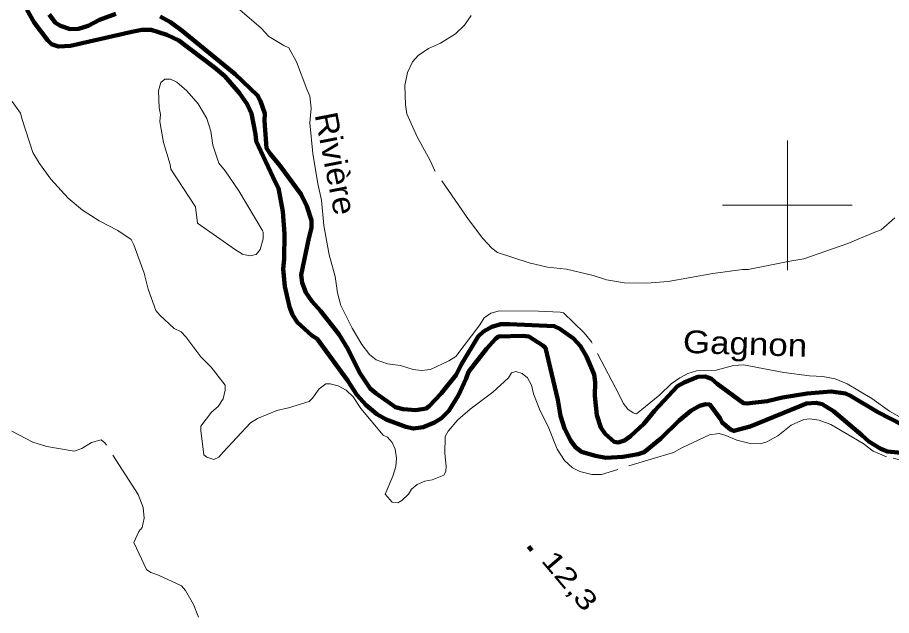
# Model space of a CAD drawing. Extents: x 386081 to 389416, y 5130568 to 5134082.
# Drawn here: x 387281.3 to 387416.1, y 5131736.8 to 5131828.9 of the extents above; entities that cross this region are included whole.
import ezdxf

# ---------------------------------------------------------------- set-up
doc = ezdxf.new("R2010")
doc.units = 0
doc.header["$LTSCALE"] = 1.2
doc.linetypes.add('DASH_DOUBLE_DOT', pattern=[9.2, 5, -1.2, 0.3, -1.2, 0.3, -1.2])
doc.linetypes.add('LONG_DASHED', pattern=[7.5, 6, -1.5])
for name, color, linetype, lineweight in [('2', 7, 'Continuous', 13), ('3', 7, 'Continuous', 140), ('4', 7, 'DASH_DOUBLE_DOT', 53), ('61', 7, 'Continuous', 13)]:
    doc.layers.add(name, color=color, linetype=linetype, lineweight=lineweight)

msp = doc.modelspace()

# ---------------------------------------------------------------- linework, layer by layer
at = {"layer": '2', "linetype": 'LONG_DASHED'}
for points in [[(387417.29, 5131767.38), (387415.75, 5131768.25), (387413.02, 5131770.2), (387409.23, 5131772.48), (387407.35, 5131773.26), (387405.46, 5131773.62), (387403.44, 5131773.7), (387399.45, 5131774.21), (387393.23, 5131775.42), (387391.71, 5131775.3), (387389.05, 5131774.59), (387385.97, 5131774.46), (387384.68, 5131774.09), (387383.41, 5131773.42), (387382.1, 5131772.48), (387380.32, 5131770.79), (387376.76, 5131767.88), (387376.23, 5131768.01), (387375.43, 5131768.57), (387374.68, 5131769.51), (387374.07, 5131770.8), (387369.79, 5131778.97), (387368.67, 5131780.36), (387365.49, 5131783.42), (387364.95, 5131783.51), (387361.65, 5131783.7), (387355.6, 5131783.74), (387354.26, 5131783.38), (387353.26, 5131782.63), (387352.58, 5131781.59), (387348.9, 5131776.68), (387347.82, 5131776.01), (387345, 5131774.68), (387343.61, 5131774.53), (387342.29, 5131774.7), (387340.37, 5131775.29), (387338.37, 5131775.58), (387336.58, 5131776.17), (387335.59, 5131777), (387334.38, 5131778.54), (387332.88, 5131781.05), (387331.18, 5131784.55), (387330.63, 5131786.49), (387330.26, 5131789.01), (387329.38, 5131792.37), (387328.56, 5131796.9), (387328.18, 5131800.79), (387327.6, 5131803.3), (387326.85, 5131808), (387326.4, 5131812.72), (387326.57, 5131814.96), (387326.39, 5131816.82), (387325.89, 5131817.88), (387324.33, 5131822.09), (387323.15, 5131824.25), (387322.35, 5131824.61), (387320.05, 5131826.03), (387318.86, 5131827.3), (387314.84, 5131830.76)], [(387372.12, 5131788.5), (387370.05, 5131789.19), (387365.93, 5131790.13), (387363.02, 5131790.48), (387360.2, 5131791.15), (387355.31, 5131792.72), (387354.42, 5131793.41), (387353.07, 5131794.9), (387350.86, 5131797.83), (387345.67, 5131805.3), (387344.93, 5131806.91), (387342.92, 5131810.57), (387341.35, 5131814.12), (387341.14, 5131815.47), (387341.03, 5131818.45), (387341.43, 5131820.48), (387342.23, 5131822.13), (387343.1, 5131823.07), (387344.68, 5131824.15), (387346.5, 5131824.99), (387348.83, 5131826.4), (387350.22, 5131827.76), (387351.24, 5131829.26)], [(387313.02, 5131770.19), (387313.33, 5131771.49), (387313.3, 5131772.26), (387311.18, 5131775.05), (387309.59, 5131776.62), (387307.27, 5131779.72), (387306.56, 5131780.5), (387305.48, 5131781.03), (387303.23, 5131783.05), (387302.61, 5131783.8), (387301.44, 5131787.05), (387300.86, 5131789.53), (387299.22, 5131793.91), (387298.85, 5131794.72), (387296.79, 5131796.13), (387293.89, 5131797.59), (387291.35, 5131799.26), (387289.14, 5131801.11), (387286.46, 5131804.01), (387284.68, 5131806.42), (387283.66, 5131808.15), (387282.01, 5131813.22), (387281.76, 5131814.22), (387280.47, 5131815.99)], [(387416.59, 5131798.07), (387414.48, 5131796.2), (387413.49, 5131795.87), (387409.33, 5131794.13), (387402.54, 5131791.76), (387400.36, 5131791.41), (387393.98, 5131790.09), (387393.1, 5131790.09), (387388.52, 5131789.48), (387381.64, 5131788.26), (387378.36, 5131787.99), (387374.91, 5131788.05), (387372.12, 5131788.5)], [(387423.34, 5131759.34), (387415.31, 5131761.25), (387413.25, 5131762.09), (387411.71, 5131763.3), (387406.68, 5131766.22), (387404.89, 5131766.86), (387403.46, 5131767.08), (387402.52, 5131766.98), (387400.61, 5131766.09), (387398.51, 5131764.46), (387396.86, 5131763.54), (387395.81, 5131763.25), (387394.26, 5131763.28), (387392.21, 5131763.78), (387390.5, 5131764.54), (387389.48, 5131764.8), (387387.99, 5131764.62), (387383.72, 5131762.62), (387382.46, 5131761.91), (387371.34, 5131758.53), (387369.88, 5131758.49), (387367.99, 5131758.98), (387366.85, 5131759.55), (387365.65, 5131760.65), (387364.51, 5131762.43), (387363.25, 5131765.63), (387361.77, 5131768.55), (387360.84, 5131770.95), (387360.53, 5131772.26), (387359.96, 5131773.38), (387359.1, 5131774.07), (387358.15, 5131774.36), (387357.46, 5131774.19), (387357.02, 5131773.38), (387354.61, 5131771.19), (387351.11, 5131768.57), (387349.22, 5131766.92), (387347.72, 5131765.17), (387347.26, 5131764.34), (387347.17, 5131761.72), (387347.39, 5131759.8), (387347.34, 5131758.97), (387347.04, 5131758.38), (387345.22, 5131757.66), (387344.09, 5131757.48), (387342.92, 5131756.95), (387342.07, 5131756.23), (387341.61, 5131755.47), (387340.55, 5131754.48), (387339.93, 5131754.12), (387339.07, 5131754.25), (387338, 5131755.48), (387339.16, 5131758.26), (387339.64, 5131759.73), (387339.76, 5131761.01), (387339.51, 5131762.42), (387339.07, 5131763.46), (387338.36, 5131764.24), (387337.66, 5131764.58), (387334.26, 5131768.7), (387333.05, 5131770.47), (387331.98, 5131771.5), (387330.73, 5131772.16), (387329.52, 5131772.49), (387328.84, 5131772.48), (387327.81, 5131771.72), (387326.8, 5131770.26), (387326.29, 5131769.76), (387323.08, 5131768.76), (387321.28, 5131768.38), (387318.33, 5131767.13), (387317.22, 5131766.49), (387312.99, 5131761.93), (387312.37, 5131761.16), (387311.57, 5131760.84), (387310.52, 5131761.16), (387310.02, 5131761.55), (387309.58, 5131765.28), (387309.57, 5131765.96), (387311.23, 5131768.09), (387312.26, 5131769.01), (387313.02, 5131770.19)], [(387309.2, 5131736.53), (387308.44, 5131738.48), (387307.19, 5131740.63), (387306.59, 5131741.36), (387303.05, 5131743.01), (387301.87, 5131743.4), (387301.21, 5131743.84), (387299.23, 5131748.01), (387300.01, 5131749.7), (387300.51, 5131750.34), (387300.81, 5131751.79), (387300.66, 5131753.42), (387299.89, 5131755.44), (387294.79, 5131763.38), (387294.2, 5131763.84), (387292.69, 5131763.45), (387291.22, 5131762.51), (387290.06, 5131762.08), (387285.84, 5131762.8), (387283.66, 5131763.5), (387280.45, 5131765.2)]]:
    msp.add_lwpolyline(points, dxfattribs=at)
msp.add_lwpolyline([(387304.97, 5131805.58), (387304.84, 5131806.26), (387303.83, 5131809.69), (387303.23, 5131812.92), (387303.36, 5131814), (387303.16, 5131815.04), (387303.02, 5131817.63), (387303.38, 5131818.92), (387304.02, 5131819.42), (387304.92, 5131819.45), (387305.89, 5131818.96), (387307.39, 5131817.66), (387309.17, 5131815.62), (387310.51, 5131813.4), (387311.12, 5131811.43), (387311.41, 5131809.29), (387312.36, 5131806.5), (387313.33, 5131805.33), (387315.43, 5131802.21), (387319.17, 5131795.91), (387319.16, 5131794.82), (387318.73, 5131793.21), (387318.09, 5131792.42), (387317.07, 5131792.2), (387315.99, 5131792.49), (387314.92, 5131793.15), (387309.04, 5131797.24), (387308.74, 5131799.78)], close=True, dxfattribs=at)
at = {"layer": '3'}
msp.add_line((387360.09, 5131747.42), (387360.6, 5131746.81), dxfattribs=at)
at = {"layer": '4', "linetype": 'Continuous', "lineweight": 90}
for points in [[(387282.76, 5131830.16), (387283.88, 5131828.16), (387286, 5131825.42), (387286.54, 5131824.84), (387287.63, 5131824.47), (387289.49, 5131824.58), (387298.91, 5131826.75), (387300.48, 5131827.05), (387301.93, 5131827.05), (387304.32, 5131826.29), (387306.17, 5131825.38), (387311.67, 5131821.24), (387313.28, 5131819.88), (387315.53, 5131817.26), (387316.71, 5131815.59), (387317.38, 5131814.13), (387318, 5131810.94), (387318.08, 5131809.9), (387321.02, 5131803.59), (387321.55, 5131802.62), (387322.2, 5131799.05), (387322.47, 5131795.59), (387322.4, 5131791.72), (387322.26, 5131790.18), (387322.53, 5131787.5), (387323.26, 5131784.37), (387323.7, 5131783.09)], [(387296.48, 5131829.53), (387293.96, 5131828.59), (387292.21, 5131827.65), (387290.71, 5131827.18), (387289.4, 5131827.16), (387287.95, 5131827.66), (387287.17, 5131828.11), (387286.2, 5131829.4)], [(387319.4, 5131813.01), (387319.42, 5131814.16), (387318.79, 5131816.04), (387318.32, 5131816.93), (387314.87, 5131820.21), (387306.67, 5131826.87), (387304.89, 5131828.24), (387303.32, 5131829.09)], [(387419.67, 5131765.17), (387413.97, 5131768.09), (387409.74, 5131770.61), (387408.95, 5131771.01), (387406.75, 5131771.3), (387403.08, 5131771.01), (387399.27, 5131770.38), (387396.89, 5131769.79), (387393.77, 5131769.47), (387393.24, 5131769.48), (387389.2, 5131772.49), (387388.3, 5131773.26), (387387.35, 5131773.59), (387386.22, 5131773.54), (387384.08, 5131772.7), (387383.06, 5131772.11), (387379.52, 5131768.33), (387377.87, 5131766.32), (387375.8, 5131764.4), (387374.91, 5131763.73), (387373.93, 5131763.45), (387373.3, 5131763.55), (387371.93, 5131764.78), (387371.23, 5131765.73), (387370.63, 5131767.67), (387370.34, 5131770.61), (387370.39, 5131772.74), (387370.22, 5131773.91), (387369.03, 5131776.7), (387368.1, 5131778.3), (387367.01, 5131779.47), (387364.91, 5131780.95), (387364.06, 5131781.38), (387357.14, 5131781.7), (387355.85, 5131781.7), (387354.43, 5131781.24), (387353.16, 5131780.53), (387352.33, 5131779.78), (387349.75, 5131775.51), (387348.93, 5131773.88), (387346.62, 5131771), (387344.76, 5131769.05), (387344.29, 5131768.66), (387342.74, 5131768.4), (387340.78, 5131768.55), (387339.56, 5131768.88), (387336.62, 5131770.97), (387335.7, 5131771.76), (387334.02, 5131774.25), (387332.23, 5131777.88), (387330.86, 5131780.16), (387328.03, 5131783.73), (387326.66, 5131785.2), (387325.77, 5131786.54), (387325.21, 5131788.07), (387325.02, 5131789.26), (387326.2, 5131794.94), (387326.62, 5131796.5), (387326.63, 5131797.63), (387325.93, 5131799.87), (387325.06, 5131801.67), (387321.76, 5131806.13), (387320.3, 5131807.87), (387319.72, 5131808.8), (387319.4, 5131813.01)], [(387323.7, 5131783.09), (387324.48, 5131781.92), (387326.71, 5131779.93), (387327.5, 5131779.4), (387332.25, 5131772.92), (387333.63, 5131770.8), (387335.06, 5131769.18), (387336.72, 5131767.82), (387338.13, 5131766.98), (387341.19, 5131765.86), (387342.34, 5131765.57), (387343.85, 5131765.8), (387345.59, 5131766.5), (387346.7, 5131767.2), (387347.79, 5131768.34), (387349.28, 5131770.74), (387350.48, 5131773.3), (387350.84, 5131774.34), (387353.59, 5131777.88), (387355.02, 5131779.42), (387355.48, 5131779.76), (387359.23, 5131779.86), (387360.12, 5131779.8), (387362.32, 5131778.4), (387362.73, 5131778.01), (387364.59, 5131770), (387365.04, 5131767.55), (387365.65, 5131765.59), (387366.61, 5131763.7), (387367.33, 5131762.72), (387368.28, 5131762.01), (387370.4, 5131761.36), (387372.02, 5131761.09), (387374.66, 5131761.24), (387376.98, 5131761.63), (387377.94, 5131761.94), (387380.5, 5131764.03), (387383.33, 5131766.82), (387385.12, 5131768.32), (387386.46, 5131769.08), (387387.42, 5131769.34), (387388.06, 5131769.29), (387389.65, 5131767.12), (387389.93, 5131766.5), (387391.22, 5131765.46), (387391.73, 5131765.23), (387394.25, 5131765.92), (387402.93, 5131769.47), (387404.45, 5131769.54), (387405.38, 5131769.34), (387407.14, 5131768.26), (387411.48, 5131764.59), (387412.54, 5131763.61), (387414.41, 5131762.47), (387415.46, 5131762.03), (387419.19, 5131761.68)]]:
    msp.add_lwpolyline(points, dxfattribs=at)
at = {"layer": '61'}
for p, q in [((387400, 5131790), (387400, 5131810)), ((387390, 5131800), (387410, 5131800))]:
    msp.add_line(p, q, dxfattribs=at)

# ---------------------------------------------------------------- texts
at = {"layer": '3', "width": 1.35}
msp.add_text('12,3   ', height=3, rotation=310.294, dxfattribs=at).set_placement((387361.92, 5131745.2))
at = {"layer": '4'}
for s, rotation, width, p in [('Rivière', 281.06, 1.1, (387327.11, 5131813.98)), ('Gagnon', 358.12, 1.15, (387383.86, 5131777.26))]:
    msp.add_text(s, height=3.5, rotation=rotation, dxfattribs=dict(at, width=width)).set_placement(p)

doc.saveas('drawing.dxf')
